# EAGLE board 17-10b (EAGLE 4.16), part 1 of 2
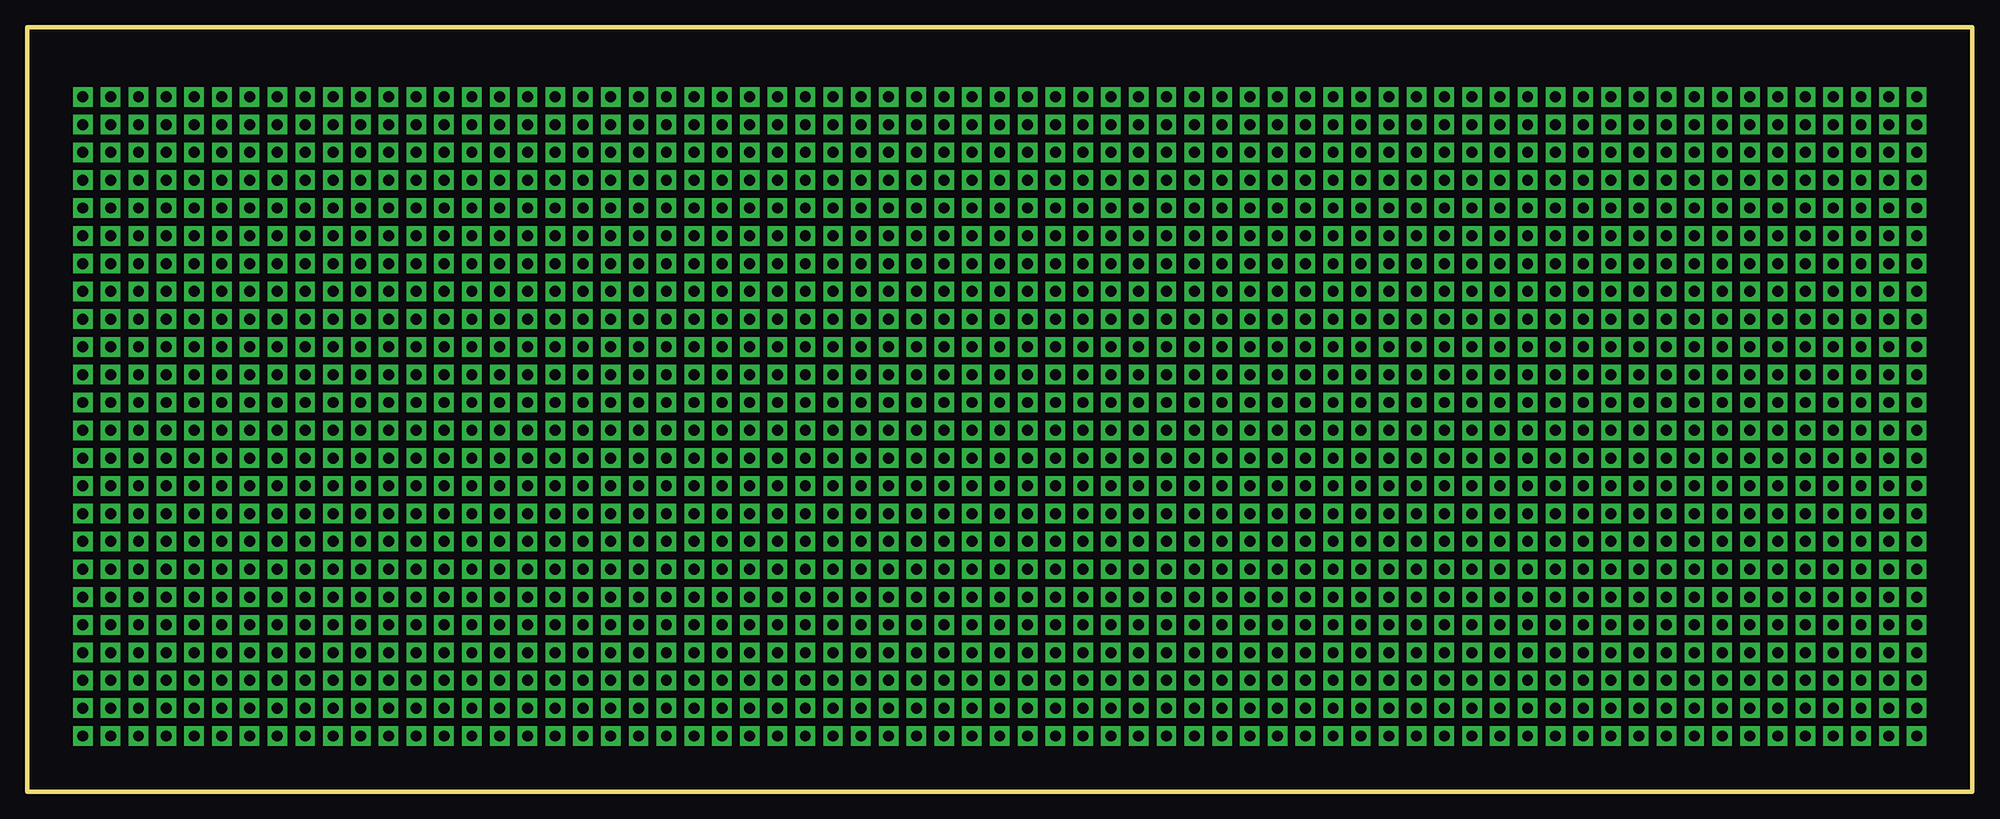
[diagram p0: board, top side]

Size 177.8 x 69.85 mm. Coordinates in mm from the lower left corner, seen from the top.
Outline: 0,0 0,69.85 177.8,69.85 177.8,0 0,0
Copper layers (1*16): Top 0.035mm / dielectric 1.5mm / Bottom 0.035mm
Design rules "default": minimum track width 10mil, minimum drill 24mil, track to track 8mil, track to pad 8mil, pad to pad 8mil, via to via 8mil, smd to smd 8mil, copper to edge 40mil, drill to drill 8mil, minimum pad ring 10mil, minimum via ring 8mil, stop-mask expansion 4mil, vias tented up to drill 0mil, thermal gap 10mil

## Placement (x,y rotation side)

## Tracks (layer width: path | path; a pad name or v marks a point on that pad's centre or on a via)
S$1  (via drill 1 pad 1.78)
  other vias: 5.08,5.08
S$2  (via drill 1 pad 1.78)
  other vias: 5.08,7.62
S$3  (via drill 1 pad 1.78)
  other vias: 5.08,10.16
S$4  (via drill 1 pad 1.78)
  other vias: 5.08,12.7
S$5  (via drill 1 pad 1.78)
  other vias: 5.08,15.24
S$6  (via drill 1 pad 1.78)
  other vias: 5.08,17.78
S$7  (via drill 1 pad 1.78)
  other vias: 5.08,20.32
S$8  (via drill 1 pad 1.78)
  other vias: 5.08,22.86
S$9  (via drill 1 pad 1.78)
  other vias: 5.08,25.4
S$10  (via drill 1 pad 1.78)
  other vias: 5.08,27.94
S$11  (via drill 1 pad 1.78)
  other vias: 5.08,30.48
S$12  (via drill 1 pad 1.78)
  other vias: 5.08,33.02
S$13  (via drill 1 pad 1.78)
  other vias: 5.08,35.56
S$14  (via drill 1 pad 1.78)
  other vias: 5.08,38.1
S$15  (via drill 1 pad 1.78)
  other vias: 5.08,40.64
S$16  (via drill 1 pad 1.78)
  other vias: 5.08,43.18
S$17  (via drill 1 pad 1.78)
  other vias: 5.08,45.72
S$18  (via drill 1 pad 1.78)
  other vias: 5.08,48.26
S$19  (via drill 1 pad 1.78)
  other vias: 5.08,50.8
S$20  (via drill 1 pad 1.78)
  other vias: 5.08,53.34
S$21  (via drill 1 pad 1.78)
  other vias: 5.08,55.88
S$22  (via drill 1 pad 1.78)
  other vias: 5.08,58.42
S$23  (via drill 1 pad 1.78)
  other vias: 5.08,60.96
S$24  (via drill 1 pad 1.78)
  other vias: 5.08,63.5
S$25  (via drill 1 pad 1.78)
  other vias: 7.62,63.5
S$26  (via drill 1 pad 1.78)
  other vias: 7.62,60.96
S$27  (via drill 1 pad 1.78)
  other vias: 7.62,58.42
S$28  (via drill 1 pad 1.78)
  other vias: 7.62,55.88
S$29  (via drill 1 pad 1.78)
  other vias: 7.62,53.34
S$30  (via drill 1 pad 1.78)
  other vias: 7.62,50.8
S$31  (via drill 1 pad 1.78)
  other vias: 7.62,48.26
S$32  (via drill 1 pad 1.78)
  other vias: 7.62,45.72
S$33  (via drill 1 pad 1.78)
  other vias: 7.62,43.18
S$34  (via drill 1 pad 1.78)
  other vias: 7.62,40.64
S$35  (via drill 1 pad 1.78)
  other vias: 7.62,38.1
S$36  (via drill 1 pad 1.78)
  other vias: 7.62,35.56
S$37  (via drill 1 pad 1.78)
  other vias: 7.62,33.02
S$38  (via drill 1 pad 1.78)
  other vias: 7.62,30.48
S$39  (via drill 1 pad 1.78)
  other vias: 7.62,27.94
S$40  (via drill 1 pad 1.78)
  other vias: 7.62,25.4
S$41  (via drill 1 pad 1.78)
  other vias: 7.62,22.86
S$42  (via drill 1 pad 1.78)
  other vias: 7.62,20.32
S$43  (via drill 1 pad 1.78)
  other vias: 7.62,17.78
S$44  (via drill 1 pad 1.78)
  other vias: 7.62,15.24
S$45  (via drill 1 pad 1.78)
  other vias: 7.62,12.7
S$46  (via drill 1 pad 1.78)
  other vias: 7.62,10.16
S$47  (via drill 1 pad 1.78)
  other vias: 7.62,7.62
S$48  (via drill 1 pad 1.78)
  other vias: 7.62,5.08
S$49  (via drill 1 pad 1.78)
  other vias: 10.16,5.08
S$50  (via drill 1 pad 1.78)
  other vias: 12.7,5.08
S$51  (via drill 1 pad 1.78)
  other vias: 15.24,5.08
S$52  (via drill 1 pad 1.78)
  other vias: 17.78,5.08
S$53  (via drill 1 pad 1.78)
  other vias: 20.32,5.08
S$54  (via drill 1 pad 1.78)
  other vias: 22.86,5.08
S$55  (via drill 1 pad 1.78)
  other vias: 25.4,5.08
S$56  (via drill 1 pad 1.78)
  other vias: 30.48,5.08
S$57  (via drill 1 pad 1.78)
  other vias: 27.94,5.08
S$58  (via drill 1 pad 1.78)
  other vias: 33.02,5.08
S$59  (via drill 1 pad 1.78)
  other vias: 38.1,5.08
S$60  (via drill 1 pad 1.78)
  other vias: 35.56,5.08
S$61  (via drill 1 pad 1.78)
  other vias: 40.64,5.08
S$62  (via drill 1 pad 1.78)
  other vias: 43.18,5.08
S$63  (via drill 1 pad 1.78)
  other vias: 45.72,5.08
S$64  (via drill 1 pad 1.78)
  other vias: 48.26,5.08
S$65  (via drill 1 pad 1.78)
  other vias: 50.8,5.08
S$66  (via drill 1 pad 1.78)
  other vias: 55.88,5.08
S$67  (via drill 1 pad 1.78)
  other vias: 53.34,5.08
S$68  (via drill 1 pad 1.78)
  other vias: 58.42,5.08
S$69  (via drill 1 pad 1.78)
  other vias: 60.96,5.08
S$70  (via drill 1 pad 1.78)
  other vias: 63.5,5.08
S$71  (via drill 1 pad 1.78)
  other vias: 66.04,5.08
S$72  (via drill 1 pad 1.78)
  other vias: 71.12,5.08
S$73  (via drill 1 pad 1.78)
  other vias: 68.58,5.08
S$74  (via drill 1 pad 1.78)
  other vias: 172.72,5.08
S$75  (via drill 1 pad 1.78)
  other vias: 172.72,7.62
S$76  (via drill 1 pad 1.78)
  other vias: 172.72,10.16
S$77  (via drill 1 pad 1.78)
  other vias: 172.72,12.7
S$78  (via drill 1 pad 1.78)
  other vias: 172.72,15.24
S$79  (via drill 1 pad 1.78)
  other vias: 172.72,17.78
S$80  (via drill 1 pad 1.78)
  other vias: 172.72,20.32
S$81  (via drill 1 pad 1.78)
  other vias: 172.72,22.86
S$82  (via drill 1 pad 1.78)
  other vias: 172.72,27.94
S$83  (via drill 1 pad 1.78)
  other vias: 172.72,25.4
S$84  (via drill 1 pad 1.78)
  other vias: 172.72,30.48
S$85  (via drill 1 pad 1.78)
  other vias: 172.72,33.02
S$86  (via drill 1 pad 1.78)
  other vias: 172.72,35.56
S$87  (via drill 1 pad 1.78)
  other vias: 172.72,38.1
S$88  (via drill 1 pad 1.78)
  other vias: 172.72,40.64
S$89  (via drill 1 pad 1.78)
  other vias: 172.72,43.18
S$90  (via drill 1 pad 1.78)
  other vias: 172.72,45.72
S$91  (via drill 1 pad 1.78)
  other vias: 172.72,48.26
S$92  (via drill 1 pad 1.78)
  other vias: 172.72,50.8
S$93  (via drill 1 pad 1.78)
  other vias: 172.72,53.34
S$94  (via drill 1 pad 1.78)
  other vias: 172.72,55.88
S$95  (via drill 1 pad 1.78)
  other vias: 172.72,58.42
S$96  (via drill 1 pad 1.78)
  other vias: 172.72,60.96
S$97  (via drill 1 pad 1.78)
  other vias: 172.72,63.5
S$98  (via drill 1 pad 1.78)
  other vias: 170.18,63.5
S$99  (via drill 1 pad 1.78)
  other vias: 167.64,63.5
S$100  (via drill 1 pad 1.78)
  other vias: 165.1,63.5
S$101  (via drill 1 pad 1.78)
  other vias: 162.56,63.5
S$102  (via drill 1 pad 1.78)
  other vias: 160.02,63.5
S$103  (via drill 1 pad 1.78)
  other vias: 157.48,63.5
S$104  (via drill 1 pad 1.78)
  other vias: 152.4,63.5
S$105  (via drill 1 pad 1.78)
  other vias: 154.94,63.5
S$106  (via drill 1 pad 1.78)
  other vias: 149.86,60.96
S$107  (via drill 1 pad 1.78)
  other vias: 149.86,63.5
S$108  (via drill 1 pad 1.78)
  other vias: 147.32,63.5
S$109  (via drill 1 pad 1.78)
  other vias: 142.24,63.5
S$110  (via drill 1 pad 1.78)
  other vias: 137.16,63.5
S$111  (via drill 1 pad 1.78)
  other vias: 132.08,63.5
S$112  (via drill 1 pad 1.78)
  other vias: 10.16,63.5
S$113  (via drill 1 pad 1.78)
  other vias: 12.7,63.5
S$114  (via drill 1 pad 1.78)
  other vias: 15.24,63.5
S$115  (via drill 1 pad 1.78)
  other vias: 17.78,60.96
S$116  (via drill 1 pad 1.78)
  other vias: 17.78,63.5
S$117  (via drill 1 pad 1.78)
  other vias: 20.32,63.5
S$118  (via drill 1 pad 1.78)
  other vias: 22.86,63.5
S$119  (via drill 1 pad 1.78)
  other vias: 25.4,63.5
S$120  (via drill 1 pad 1.78)
  other vias: 27.94,60.96
S$121  (via drill 1 pad 1.78)
  other vias: 27.94,63.5
S$122  (via drill 1 pad 1.78)
  other vias: 30.48,63.5
S$123  (via drill 1 pad 1.78)
  other vias: 33.02,63.5
S$124  (via drill 1 pad 1.78)
  other vias: 35.56,63.5
S$125  (via drill 1 pad 1.78)
  other vias: 38.1,63.5
S$126  (via drill 1 pad 1.78)
  other vias: 40.64,63.5
S$127  (via drill 1 pad 1.78)
  other vias: 43.18,63.5
S$128  (via drill 1 pad 1.78)
  other vias: 45.72,63.5
S$129  (via drill 1 pad 1.78)
  other vias: 48.26,63.5
S$130  (via drill 1 pad 1.78)
  other vias: 50.8,63.5
S$131  (via drill 1 pad 1.78)
  other vias: 53.34,63.5
S$132  (via drill 1 pad 1.78)
  other vias: 55.88,63.5
S$133  (via drill 1 pad 1.78)
  other vias: 58.42,63.5
S$134  (via drill 1 pad 1.78)
  other vias: 63.5,63.5
S$135  (via drill 1 pad 1.78)
  other vias: 66.04,63.5
S$136  (via drill 1 pad 1.78)
  other vias: 68.58,60.96
S$137  (via drill 1 pad 1.78)
  other vias: 73.66,63.5
S$138  (via drill 1 pad 1.78)
  other vias: 81.28,63.5
S$139  (via drill 1 pad 1.78)
  other vias: 81.28,60.96
S$140  (via drill 1 pad 1.78)
  other vias: 96.52,63.5
S$141  (via drill 1 pad 1.78)
  other vias: 101.6,60.96
S$142  (via drill 1 pad 1.78)
  other vias: 111.76,60.96
S$143  (via drill 1 pad 1.78)
  other vias: 114.3,60.96
S$144  (via drill 1 pad 1.78)
  other vias: 129.54,63.5
S$145  (via drill 1 pad 1.78)
  other vias: 127,63.5
S$146  (via drill 1 pad 1.78)
  other vias: 124.46,63.5
S$147  (via drill 1 pad 1.78)
  other vias: 121.92,63.5
S$148  (via drill 1 pad 1.78)
  other vias: 116.84,63.5
S$149  (via drill 1 pad 1.78)
  other vias: 119.38,63.5
S$150  (via drill 1 pad 1.78)
  other vias: 114.3,63.5
S$151  (via drill 1 pad 1.78)
  other vias: 111.76,63.5
S$152  (via drill 1 pad 1.78)
  other vias: 109.22,63.5
S$153  (via drill 1 pad 1.78)
  other vias: 106.68,63.5
S$154  (via drill 1 pad 1.78)
  other vias: 104.14,63.5
S$155  (via drill 1 pad 1.78)
  other vias: 101.6,63.5
S$156  (via drill 1 pad 1.78)
  other vias: 99.06,63.5
S$157  (via drill 1 pad 1.78)
  other vias: 93.98,63.5
S$158  (via drill 1 pad 1.78)
  other vias: 91.44,63.5
S$159  (via drill 1 pad 1.78)
  other vias: 88.9,63.5
S$160  (via drill 1 pad 1.78)
  other vias: 86.36,63.5
S$161  (via drill 1 pad 1.78)
  other vias: 83.82,63.5
S$162  (via drill 1 pad 1.78)
  other vias: 78.74,63.5
S$163  (via drill 1 pad 1.78)
  other vias: 76.2,63.5
S$164  (via drill 1 pad 1.78)
  other vias: 71.12,63.5
S$165  (via drill 1 pad 1.78)
  other vias: 68.58,63.5
S$166  (via drill 1 pad 1.78)
  other vias: 60.96,63.5
S$167  (via drill 1 pad 1.78)
  other vias: 134.62,63.5
S$168  (via drill 1 pad 1.78)
  other vias: 139.7,63.5
S$169  (via drill 1 pad 1.78)
  other vias: 144.78,63.5
S$170  (via drill 1 pad 1.78)
  other vias: 73.66,5.08
S$171  (via drill 1 pad 1.78)
  other vias: 76.2,5.08
S$172  (via drill 1 pad 1.78)
  other vias: 78.74,5.08
S$173  (via drill 1 pad 1.78)
  other vias: 81.28,5.08
S$174  (via drill 1 pad 1.78)
  other vias: 83.82,5.08
S$175  (via drill 1 pad 1.78)
  other vias: 86.36,5.08
S$176  (via drill 1 pad 1.78)
  other vias: 88.9,5.08
S$177  (via drill 1 pad 1.78)
  other vias: 91.44,5.08
S$178  (via drill 1 pad 1.78)
  other vias: 93.98,5.08
S$179  (via drill 1 pad 1.78)
  other vias: 96.52,5.08
S$180  (via drill 1 pad 1.78)
  other vias: 99.06,5.08
S$181  (via drill 1 pad 1.78)
  other vias: 101.6,5.08
S$182  (via drill 1 pad 1.78)
  other vias: 170.18,5.08
S$183  (via drill 1 pad 1.78)
  other vias: 167.64,5.08
S$184  (via drill 1 pad 1.78)
  other vias: 165.1,5.08
S$185  (via drill 1 pad 1.78)
  other vias: 162.56,5.08
S$186  (via drill 1 pad 1.78)
  other vias: 160.02,5.08
S$187  (via drill 1 pad 1.78)
  other vias: 157.48,5.08
S$188  (via drill 1 pad 1.78)
  other vias: 154.94,5.08
S$189  (via drill 1 pad 1.78)
  other vias: 152.4,5.08
S$190  (via drill 1 pad 1.78)
  other vias: 149.86,5.08
S$191  (via drill 1 pad 1.78)
  other vias: 147.32,5.08
S$192  (via drill 1 pad 1.78)
  other vias: 144.78,5.08
S$193  (via drill 1 pad 1.78)
  other vias: 142.24,5.08
S$194  (via drill 1 pad 1.78)
  other vias: 139.7,5.08
S$195  (via drill 1 pad 1.78)
  other vias: 137.16,5.08
S$196  (via drill 1 pad 1.78)
  other vias: 134.62,5.08
S$197  (via drill 1 pad 1.78)
  other vias: 132.08,5.08
S$198  (via drill 1 pad 1.78)
  other vias: 129.54,5.08
S$199  (via drill 1 pad 1.78)
  other vias: 127,5.08
S$200  (via drill 1 pad 1.78)
  other vias: 124.46,5.08
S$201  (via drill 1 pad 1.78)
  other vias: 121.92,5.08
S$202  (via drill 1 pad 1.78)
  other vias: 119.38,5.08
S$203  (via drill 1 pad 1.78)
  other vias: 116.84,5.08
S$204  (via drill 1 pad 1.78)
  other vias: 114.3,5.08
S$205  (via drill 1 pad 1.78)
  other vias: 111.76,5.08
S$206  (via drill 1 pad 1.78)
  other vias: 109.22,5.08
S$207  (via drill 1 pad 1.78)
  other vias: 106.68,5.08
S$208  (via drill 1 pad 1.78)
  other vias: 104.14,5.08
S$209  (via drill 1 pad 1.78)
  other vias: 170.18,60.96
S$210  (via drill 1 pad 1.78)
  other vias: 170.18,58.42
S$211  (via drill 1 pad 1.78)
  other vias: 170.18,55.88
S$212  (via drill 1 pad 1.78)
  other vias: 170.18,53.34
S$213  (via drill 1 pad 1.78)
  other vias: 170.18,50.8
S$214  (via drill 1 pad 1.78)
  other vias: 170.18,48.26
S$215  (via drill 1 pad 1.78)
  other vias: 170.18,45.72
S$216  (via drill 1 pad 1.78)
  other vias: 170.18,43.18
S$217  (via drill 1 pad 1.78)
  other vias: 170.18,40.64
S$218  (via drill 1 pad 1.78)
  other vias: 170.18,38.1
S$219  (via drill 1 pad 1.78)
  other vias: 170.18,35.56
S$220  (via drill 1 pad 1.78)
  other vias: 170.18,33.02
S$221  (via drill 1 pad 1.78)
  other vias: 170.18,30.48
S$222  (via drill 1 pad 1.78)
  other vias: 170.18,27.94
S$223  (via drill 1 pad 1.78)
  other vias: 170.18,25.4
S$224  (via drill 1 pad 1.78)
  other vias: 170.18,22.86
S$225  (via drill 1 pad 1.78)
  other vias: 170.18,20.32
S$226  (via drill 1 pad 1.78)
  other vias: 170.18,17.78
S$227  (via drill 1 pad 1.78)
  other vias: 170.18,15.24
S$228  (via drill 1 pad 1.78)
  other vias: 170.18,12.7
S$229  (via drill 1 pad 1.78)
  other vias: 170.18,10.16
S$230  (via drill 1 pad 1.78)
  other vias: 170.18,7.62
S$231  (via drill 1 pad 1.78)
  other vias: 167.64,7.62
S$232  (via drill 1 pad 1.78)
  other vias: 165.1,7.62
S$233  (via drill 1 pad 1.78)
  other vias: 162.56,7.62
S$234  (via drill 1 pad 1.78)
  other vias: 157.48,7.62
S$235  (via drill 1 pad 1.78)
  other vias: 160.02,7.62
S$236  (via drill 1 pad 1.78)
  other vias: 154.94,7.62
S$237  (via drill 1 pad 1.78)
  other vias: 152.4,7.62
S$238  (via drill 1 pad 1.78)
  other vias: 149.86,7.62
S$239  (via drill 1 pad 1.78)
  other vias: 147.32,7.62
S$240  (via drill 1 pad 1.78)
  other vias: 144.78,7.62
S$241  (via drill 1 pad 1.78)
  other vias: 12.7,7.62
S$242  (via drill 1 pad 1.78)
  other vias: 10.16,7.62
S$243  (via drill 1 pad 1.78)
  other vias: 15.24,7.62
S$244  (via drill 1 pad 1.78)
  other vias: 17.78,7.62
S$245  (via drill 1 pad 1.78)
  other vias: 20.32,7.62
S$246  (via drill 1 pad 1.78)
  other vias: 22.86,7.62
S$247  (via drill 1 pad 1.78)
  other vias: 25.4,7.62
S$248  (via drill 1 pad 1.78)
  other vias: 27.94,7.62
S$249  (via drill 1 pad 1.78)
  other vias: 30.48,7.62
S$250  (via drill 1 pad 1.78)
  other vias: 33.02,7.62
S$251  (via drill 1 pad 1.78)
  other vias: 35.56,7.62
S$252  (via drill 1 pad 1.78)
  other vias: 38.1,7.62
S$253  (via drill 1 pad 1.78)
  other vias: 40.64,7.62
S$254  (via drill 1 pad 1.78)
  other vias: 43.18,7.62
S$255  (via drill 1 pad 1.78)
  other vias: 45.72,7.62
S$256  (via drill 1 pad 1.78)
  other vias: 48.26,7.62
S$257  (via drill 1 pad 1.78)
  other vias: 50.8,7.62
S$258  (via drill 1 pad 1.78)
  other vias: 53.34,7.62
S$259  (via drill 1 pad 1.78)
  other vias: 55.88,7.62
S$260  (via drill 1 pad 1.78)
  other vias: 58.42,7.62
S$261  (via drill 1 pad 1.78)
  other vias: 60.96,7.62
S$262  (via drill 1 pad 1.78)
  other vias: 63.5,7.62
S$263  (via drill 1 pad 1.78)
  other vias: 66.04,7.62
S$264  (via drill 1 pad 1.78)
  other vias: 68.58,7.62
S$265  (via drill 1 pad 1.78)
  other vias: 71.12,7.62
S$266  (via drill 1 pad 1.78)
  other vias: 73.66,7.62
S$267  (via drill 1 pad 1.78)
  other vias: 76.2,7.62
S$268  (via drill 1 pad 1.78)
  other vias: 78.74,7.62
S$269  (via drill 1 pad 1.78)
  other vias: 81.28,7.62
S$270  (via drill 1 pad 1.78)
  other vias: 86.36,7.62
S$271  (via drill 1 pad 1.78)
  other vias: 83.82,7.62
S$272  (via drill 1 pad 1.78)
  other vias: 88.9,7.62
S$273  (via drill 1 pad 1.78)
  other vias: 91.44,7.62
S$274  (via drill 1 pad 1.78)
  other vias: 93.98,7.62
S$275  (via drill 1 pad 1.78)
  other vias: 96.52,7.62
S$276  (via drill 1 pad 1.78)
  other vias: 99.06,7.62
S$277  (via drill 1 pad 1.78)
  other vias: 101.6,7.62
S$278  (via drill 1 pad 1.78)
  other vias: 104.14,7.62
S$279  (via drill 1 pad 1.78)
  other vias: 109.22,7.62
S$280  (via drill 1 pad 1.78)
  other vias: 106.68,7.62
S$281  (via drill 1 pad 1.78)
  other vias: 111.76,7.62
S$282  (via drill 1 pad 1.78)
  other vias: 114.3,7.62
S$283  (via drill 1 pad 1.78)
  other vias: 142.24,7.62
S$284  (via drill 1 pad 1.78)
  other vias: 139.7,7.62
S$285  (via drill 1 pad 1.78)
  other vias: 137.16,7.62
S$286  (via drill 1 pad 1.78)
  other vias: 134.62,7.62
S$287  (via drill 1 pad 1.78)
  other vias: 132.08,7.62
S$288  (via drill 1 pad 1.78)
  other vias: 129.54,7.62
S$289  (via drill 1 pad 1.78)
  other vias: 127,7.62
S$290  (via drill 1 pad 1.78)
  other vias: 124.46,7.62
S$291  (via drill 1 pad 1.78)
  other vias: 121.92,7.62
S$292  (via drill 1 pad 1.78)
  other vias: 119.38,7.62
S$293  (via drill 1 pad 1.78)
  other vias: 116.84,7.62
S$294  (via drill 1 pad 1.78)
  other vias: 10.16,60.96
S$295  (via drill 1 pad 1.78)
  other vias: 12.7,60.96
S$296  (via drill 1 pad 1.78)
  other vias: 15.24,60.96
S$297  (via drill 1 pad 1.78)
  other vias: 20.32,60.96
S$298  (via drill 1 pad 1.78)
  other vias: 22.86,60.96
S$299  (via drill 1 pad 1.78)
  other vias: 25.4,60.96
S$300  (via drill 1 pad 1.78)
  other vias: 30.48,60.96
S$301  (via drill 1 pad 1.78)
  other vias: 33.02,60.96
S$302  (via drill 1 pad 1.78)
  other vias: 35.56,60.96
S$303  (via drill 1 pad 1.78)
  other vias: 38.1,60.96
S$304  (via drill 1 pad 1.78)
  other vias: 40.64,60.96
S$305  (via drill 1 pad 1.78)
  other vias: 43.18,60.96
S$306  (via drill 1 pad 1.78)
  other vias: 45.72,60.96
S$307  (via drill 1 pad 1.78)
  other vias: 48.26,60.96
S$308  (via drill 1 pad 1.78)
  other vias: 50.8,60.96
S$309  (via drill 1 pad 1.78)
  other vias: 53.34,60.96
S$310  (via drill 1 pad 1.78)
  other vias: 55.88,60.96
S$311  (via drill 1 pad 1.78)
  other vias: 58.42,60.96
S$312  (via drill 1 pad 1.78)
  other vias: 60.96,60.96
S$313  (via drill 1 pad 1.78)
  other vias: 63.5,60.96
S$314  (via drill 1 pad 1.78)
  other vias: 66.04,60.96
S$315  (via drill 1 pad 1.78)
  other vias: 71.12,60.96
S$316  (via drill 1 pad 1.78)
  other vias: 73.66,60.96
S$317  (via drill 1 pad 1.78)
  other vias: 76.2,60.96
S$318  (via drill 1 pad 1.78)
  other vias: 78.74,60.96
S$319  (via drill 1 pad 1.78)
  other vias: 83.82,60.96
S$320  (via drill 1 pad 1.78)
  other vias: 86.36,60.96
S$321  (via drill 1 pad 1.78)
  other vias: 88.9,60.96
S$322  (via drill 1 pad 1.78)
  other vias: 91.44,60.96
S$323  (via drill 1 pad 1.78)
  other vias: 93.98,60.96
S$324  (via drill 1 pad 1.78)
  other vias: 96.52,60.96
S$325  (via drill 1 pad 1.78)
  other vias: 99.06,60.96
S$326  (via drill 1 pad 1.78)
  other vias: 104.14,60.96
S$327  (via drill 1 pad 1.78)
  other vias: 106.68,60.96
S$328  (via drill 1 pad 1.78)
  other vias: 109.22,60.96
S$329  (via drill 1 pad 1.78)
  other vias: 116.84,60.96
S$330  (via drill 1 pad 1.78)
  other vias: 167.64,60.96
S$331  (via drill 1 pad 1.78)
  other vias: 165.1,60.96
S$332  (via drill 1 pad 1.78)
  other vias: 162.56,60.96
S$333  (via drill 1 pad 1.78)
  other vias: 160.02,60.96
S$334  (via drill 1 pad 1.78)
  other vias: 157.48,60.96
S$335  (via drill 1 pad 1.78)
  other vias: 154.94,60.96
S$336  (via drill 1 pad 1.78)
  other vias: 152.4,60.96
S$337  (via drill 1 pad 1.78)
  other vias: 147.32,60.96
S$338  (via drill 1 pad 1.78)
  other vias: 144.78,60.96
S$339  (via drill 1 pad 1.78)
  other vias: 142.24,60.96
S$340  (via drill 1 pad 1.78)
  other vias: 139.7,60.96
S$341  (via drill 1 pad 1.78)
  other vias: 137.16,60.96
S$342  (via drill 1 pad 1.78)
  other vias: 134.62,60.96
S$343  (via drill 1 pad 1.78)
  other vias: 132.08,60.96
S$344  (via drill 1 pad 1.78)
  other vias: 129.54,60.96
S$345  (via drill 1 pad 1.78)
  other vias: 127,60.96
S$346  (via drill 1 pad 1.78)
  other vias: 124.46,60.96
S$347  (via drill 1 pad 1.78)
  other vias: 121.92,60.96
S$348  (via drill 1 pad 1.78)
  other vias: 119.38,60.96
S$349  (via drill 1 pad 1.78)
  other vias: 167.64,58.42
S$350  (via drill 1 pad 1.78)
  other vias: 167.64,55.88
S$351  (via drill 1 pad 1.78)
  other vias: 167.64,53.34
S$352  (via drill 1 pad 1.78)
  other vias: 167.64,50.8
S$353  (via drill 1 pad 1.78)
  other vias: 167.64,48.26
S$354  (via drill 1 pad 1.78)
  other vias: 167.64,45.72
S$355  (via drill 1 pad 1.78)
  other vias: 167.64,43.18
S$356  (via drill 1 pad 1.78)
  other vias: 167.64,40.64
S$357  (via drill 1 pad 1.78)
  other vias: 167.64,38.1
S$358  (via drill 1 pad 1.78)
  other vias: 167.64,33.02
S$359  (via drill 1 pad 1.78)
  other vias: 167.64,35.56
S$360  (via drill 1 pad 1.78)
  other vias: 167.64,30.48
S$361  (via drill 1 pad 1.78)
  other vias: 167.64,27.94
S$362  (via drill 1 pad 1.78)
  other vias: 167.64,25.4
S$363  (via drill 1 pad 1.78)
  other vias: 167.64,22.86
S$364  (via drill 1 pad 1.78)
  other vias: 167.64,20.32
S$365  (via drill 1 pad 1.78)
  other vias: 167.64,17.78
S$366  (via drill 1 pad 1.78)
  other vias: 167.64,15.24
S$367  (via drill 1 pad 1.78)
  other vias: 167.64,12.7
S$368  (via drill 1 pad 1.78)
  other vias: 167.64,10.16
S$369  (via drill 1 pad 1.78)
  other vias: 10.16,58.42
S$370  (via drill 1 pad 1.78)
  other vias: 10.16,53.34
S$371  (via drill 1 pad 1.78)
  other vias: 10.16,55.88
S$372  (via drill 1 pad 1.78)
  other vias: 10.16,50.8
S$373  (via drill 1 pad 1.78)
  other vias: 10.16,48.26
S$374  (via drill 1 pad 1.78)
  other vias: 10.16,45.72
S$375  (via drill 1 pad 1.78)
  other vias: 10.16,43.18
S$376  (via drill 1 pad 1.78)
  other vias: 10.16,40.64
S$377  (via drill 1 pad 1.78)
  other vias: 10.16,38.1
S$378  (via drill 1 pad 1.78)
  other vias: 10.16,35.56
S$379  (via drill 1 pad 1.78)
  other vias: 10.16,33.02
S$380  (via drill 1 pad 1.78)
  other vias: 10.16,30.48
S$381  (via drill 1 pad 1.78)
  other vias: 10.16,27.94
S$382  (via drill 1 pad 1.78)
  other vias: 10.16,25.4
S$383  (via drill 1 pad 1.78)
  other vias: 10.16,22.86
S$384  (via drill 1 pad 1.78)
  other vias: 10.16,20.32
S$385  (via drill 1 pad 1.78)
  other vias: 10.16,17.78
S$386  (via drill 1 pad 1.78)
  other vias: 10.16,15.24
S$387  (via drill 1 pad 1.78)
  other vias: 10.16,12.7
S$388  (via drill 1 pad 1.78)
  other vias: 12.7,10.16
S$389  (via drill 1 pad 1.78)
  other vias: 10.16,10.16
S$390  (via drill 1 pad 1.78)
  other vias: 15.24,10.16
S$391  (via drill 1 pad 1.78)
  other vias: 17.78,10.16
S$392  (via drill 1 pad 1.78)
  other vias: 20.32,10.16
S$393  (via drill 1 pad 1.78)
  other vias: 22.86,10.16
S$394  (via drill 1 pad 1.78)
  other vias: 25.4,10.16
S$395  (via drill 1 pad 1.78)
  other vias: 27.94,10.16
S$396  (via drill 1 pad 1.78)
  other vias: 30.48,10.16
S$397  (via drill 1 pad 1.78)
  other vias: 33.02,10.16
S$398  (via drill 1 pad 1.78)
  other vias: 35.56,10.16
S$399  (via drill 1 pad 1.78)
  other vias: 38.1,10.16
S$400  (via drill 1 pad 1.78)
  other vias: 40.64,10.16
S$401  (via drill 1 pad 1.78)
  other vias: 43.18,10.16
S$402  (via drill 1 pad 1.78)
  other vias: 45.72,10.16
S$403  (via drill 1 pad 1.78)
  other vias: 50.8,10.16
S$404  (via drill 1 pad 1.78)
  other vias: 48.26,10.16
S$405  (via drill 1 pad 1.78)
  other vias: 53.34,10.16
S$406  (via drill 1 pad 1.78)
  other vias: 55.88,10.16
S$407  (via drill 1 pad 1.78)
  other vias: 58.42,10.16
S$408  (via drill 1 pad 1.78)
  other vias: 60.96,10.16
S$409  (via drill 1 pad 1.78)
  other vias: 63.5,10.16
S$410  (via drill 1 pad 1.78)
  other vias: 68.58,10.16
S$411  (via drill 1 pad 1.78)
  other vias: 66.04,10.16
S$412  (via drill 1 pad 1.78)
  other vias: 73.66,10.16
S$413  (via drill 1 pad 1.78)
  other vias: 71.12,10.16
S$414  (via drill 1 pad 1.78)
  other vias: 76.2,10.16
S$415  (via drill 1 pad 1.78)
  other vias: 78.74,10.16
S$416  (via drill 1 pad 1.78)
  other vias: 81.28,10.16
S$417  (via drill 1 pad 1.78)
  other vias: 83.82,10.16
S$418  (via drill 1 pad 1.78)
  other vias: 86.36,10.16
S$419  (via drill 1 pad 1.78)
  other vias: 88.9,10.16
S$420  (via drill 1 pad 1.78)
  other vias: 91.44,10.16
S$421  (via drill 1 pad 1.78)
  other vias: 93.98,10.16
S$422  (via drill 1 pad 1.78)
  other vias: 96.52,10.16
S$423  (via drill 1 pad 1.78)
  other vias: 99.06,10.16
S$424  (via drill 1 pad 1.78)
  other vias: 101.6,10.16
S$425  (via drill 1 pad 1.78)
  other vias: 104.14,10.16
S$426  (via drill 1 pad 1.78)
  other vias: 106.68,10.16
S$427  (via drill 1 pad 1.78)
  other vias: 109.22,10.16
S$428  (via drill 1 pad 1.78)
  other vias: 111.76,10.16
S$429  (via drill 1 pad 1.78)
  other vias: 114.3,10.16
S$430  (via drill 1 pad 1.78)
  other vias: 116.84,10.16
S$431  (via drill 1 pad 1.78)
  other vias: 119.38,10.16
S$432  (via drill 1 pad 1.78)
  other vias: 121.92,10.16
S$433  (via drill 1 pad 1.78)
  other vias: 127,10.16
S$434  (via drill 1 pad 1.78)
  other vias: 124.46,10.16
S$435  (via drill 1 pad 1.78)
  other vias: 129.54,10.16
S$436  (via drill 1 pad 1.78)
  other vias: 132.08,10.16
S$437  (via drill 1 pad 1.78)
  other vias: 134.62,10.16
S$438  (via drill 1 pad 1.78)
  other vias: 137.16,10.16
S$439  (via drill 1 pad 1.78)
  other vias: 139.7,10.16
S$440  (via drill 1 pad 1.78)
  other vias: 142.24,10.16
S$441  (via drill 1 pad 1.78)
  other vias: 144.78,10.16
S$442  (via drill 1 pad 1.78)
  other vias: 147.32,10.16
S$443  (via drill 1 pad 1.78)
  other vias: 149.86,10.16
S$444  (via drill 1 pad 1.78)
  other vias: 152.4,10.16
S$445  (via drill 1 pad 1.78)
  other vias: 157.48,10.16
S$446  (via drill 1 pad 1.78)
  other vias: 154.94,10.16
S$447  (via drill 1 pad 1.78)
  other vias: 160.02,10.16
S$448  (via drill 1 pad 1.78)
  other vias: 162.56,10.16
S$449  (via drill 1 pad 1.78)
  other vias: 165.1,10.16
S$450  (via drill 1 pad 1.78)
  other vias: 165.1,58.42
S$451  (via drill 1 pad 1.78)
  other vias: 162.56,58.42
S$452  (via drill 1 pad 1.78)
  other vias: 160.02,58.42
S$453  (via drill 1 pad 1.78)
  other vias: 157.48,58.42
S$454  (via drill 1 pad 1.78)
  other vias: 154.94,58.42
S$455  (via drill 1 pad 1.78)
  other vias: 152.4,58.42
S$456  (via drill 1 pad 1.78)
  other vias: 149.86,58.42
S$457  (via drill 1 pad 1.78)
  other vias: 144.78,58.42
S$458  (via drill 1 pad 1.78)
  other vias: 147.32,58.42
S$459  (via drill 1 pad 1.78)
  other vias: 144.78,55.88
S$460  (via drill 1 pad 1.78)
  other vias: 142.24,58.42
S$461  (via drill 1 pad 1.78)
  other vias: 139.7,58.42
S$462  (via drill 1 pad 1.78)
  other vias: 12.7,58.42
S$463  (via drill 1 pad 1.78)
  other vias: 15.24,58.42
S$464  (via drill 1 pad 1.78)
  other vias: 17.78,58.42
S$465  (via drill 1 pad 1.78)
  other vias: 20.32,58.42
S$466  (via drill 1 pad 1.78)
  other vias: 22.86,58.42
S$467  (via drill 1 pad 1.78)
  other vias: 25.4,58.42
S$468  (via drill 1 pad 1.78)
  other vias: 30.48,58.42
S$469  (via drill 1 pad 1.78)
  other vias: 27.94,58.42
S$470  (via drill 1 pad 1.78)
  other vias: 33.02,58.42
S$471  (via drill 1 pad 1.78)
  other vias: 35.56,55.88
S$472  (via drill 1 pad 1.78)
  other vias: 35.56,58.42
S$473  (via drill 1 pad 1.78)
  other vias: 38.1,58.42
S$474  (via drill 1 pad 1.78)
  other vias: 40.64,58.42
S$475  (via drill 1 pad 1.78)
  other vias: 43.18,58.42
S$476  (via drill 1 pad 1.78)
  other vias: 45.72,58.42
S$477  (via drill 1 pad 1.78)
  other vias: 48.26,58.42
S$478  (via drill 1 pad 1.78)
  other vias: 50.8,58.42
S$479  (via drill 1 pad 1.78)
  other vias: 53.34,58.42
S$480  (via drill 1 pad 1.78)
  other vias: 55.88,58.42
S$481  (via drill 1 pad 1.78)
  other vias: 58.42,58.42
S$482  (via drill 1 pad 1.78)
  other vias: 60.96,58.42
S$483  (via drill 1 pad 1.78)
  other vias: 63.5,58.42
S$484  (via drill 1 pad 1.78)
  other vias: 66.04,58.42
S$485  (via drill 1 pad 1.78)
  other vias: 68.58,55.88
S$486  (via drill 1 pad 1.78)
  other vias: 71.12,58.42
S$487  (via drill 1 pad 1.78)
  other vias: 73.66,58.42
S$488  (via drill 1 pad 1.78)
  other vias: 76.2,58.42
S$489  (via drill 1 pad 1.78)
  other vias: 68.58,58.42
S$490  (via drill 1 pad 1.78)
  other vias: 78.74,58.42
S$491  (via drill 1 pad 1.78)
  other vias: 81.28,58.42
S$492  (via drill 1 pad 1.78)
  other vias: 83.82,58.42
S$493  (via drill 1 pad 1.78)
  other vias: 86.36,58.42
S$494  (via drill 1 pad 1.78)
  other vias: 88.9,58.42
S$495  (via drill 1 pad 1.78)
  other vias: 91.44,55.88
S$496  (via drill 1 pad 1.78)
  other vias: 93.98,55.88
S$497  (via drill 1 pad 1.78)
  other vias: 81.28,40.64
S$498  (via drill 1 pad 1.78)
  other vias: 60.96,27.94
S$499  (via drill 1 pad 1.78)
  other vias: 78.74,20.32
S$500  (via drill 1 pad 1.78)
  other vias: 86.36,22.86
S$501  (via drill 1 pad 1.78)
  other vias: 93.98,27.94
S$502  (via drill 1 pad 1.78)
  other vias: 99.06,30.48
S$503  (via drill 1 pad 1.78)
  other vias: 99.06,35.56
S$504  (via drill 1 pad 1.78)
  other vias: 93.98,40.64
S$505  (via drill 1 pad 1.78)
  other vias: 40.64,38.1
S$506  (via drill 1 pad 1.78)
  other vias: 35.56,35.56
S$507  (via drill 1 pad 1.78)
  other vias: 30.48,33.02
S$508  (via drill 1 pad 1.78)
  other vias: 27.94,33.02
S$509  (via drill 1 pad 1.78)
  other vias: 25.4,48.26
S$510  (via drill 1 pad 1.78)
  other vias: 25.4,45.72
S$511  (via drill 1 pad 1.78)
  other vias: 91.44,58.42
S$512  (via drill 1 pad 1.78)
  other vias: 93.98,58.42
S$513  (via drill 1 pad 1.78)
  other vias: 96.52,58.42
S$514  (via drill 1 pad 1.78)
  other vias: 99.06,58.42
S$515  (via drill 1 pad 1.78)
  other vias: 101.6,58.42
S$516  (via drill 1 pad 1.78)
  other vias: 104.14,58.42
S$517  (via drill 1 pad 1.78)
  other vias: 106.68,58.42
S$518  (via drill 1 pad 1.78)
  other vias: 109.22,58.42
S$519  (via drill 1 pad 1.78)
  other vias: 111.76,55.88
S$520  (via drill 1 pad 1.78)
  other vias: 111.76,58.42
S$521  (via drill 1 pad 1.78)
  other vias: 116.84,58.42
S$522  (via drill 1 pad 1.78)
  other vias: 114.3,58.42
S$523  (via drill 1 pad 1.78)
  other vias: 119.38,58.42
S$524  (via drill 1 pad 1.78)
  other vias: 124.46,58.42
S$525  (via drill 1 pad 1.78)
  other vias: 121.92,58.42
S$526  (via drill 1 pad 1.78)
  other vias: 127,58.42
S$527  (via drill 1 pad 1.78)
  other vias: 129.54,58.42
S$528  (via drill 1 pad 1.78)
  other vias: 134.62,58.42
S$529  (via drill 1 pad 1.78)
  other vias: 132.08,58.42
S$530  (via drill 1 pad 1.78)
  other vias: 137.16,58.42
S$531  (via drill 1 pad 1.78)
  other vias: 12.7,55.88
S$532  (via drill 1 pad 1.78)
  other vias: 15.24,55.88
S$533  (via drill 1 pad 1.78)
  other vias: 17.78,55.88
S$534  (via drill 1 pad 1.78)
  other vias: 20.32,55.88
S$535  (via drill 1 pad 1.78)
  other vias: 22.86,53.34
S$536  (via drill 1 pad 1.78)
  other vias: 22.86,55.88
S$537  (via drill 1 pad 1.78)
  other vias: 25.4,55.88
S$538  (via drill 1 pad 1.78)
  other vias: 27.94,55.88
S$539  (via drill 1 pad 1.78)
  other vias: 30.48,55.88
S$540  (via drill 1 pad 1.78)
  other vias: 33.02,55.88
S$541  (via drill 1 pad 1.78)
  other vias: 38.1,55.88
S$542  (via drill 1 pad 1.78)
  other vias: 40.64,55.88
S$543  (via drill 1 pad 1.78)
  other vias: 43.18,55.88
S$544  (via drill 1 pad 1.78)
  other vias: 45.72,55.88
S$545  (via drill 1 pad 1.78)
  other vias: 48.26,55.88
S$546  (via drill 1 pad 1.78)
  other vias: 50.8,55.88
S$547  (via drill 1 pad 1.78)
  other vias: 53.34,55.88
S$548  (via drill 1 pad 1.78)
  other vias: 55.88,55.88
S$549  (via drill 1 pad 1.78)
  other vias: 58.42,55.88
S$550  (via drill 1 pad 1.78)
  other vias: 60.96,55.88
S$551  (via drill 1 pad 1.78)
  other vias: 63.5,55.88
S$552  (via drill 1 pad 1.78)
  other vias: 66.04,55.88
S$553  (via drill 1 pad 1.78)
  other vias: 71.12,55.88
S$554  (via drill 1 pad 1.78)
  other vias: 73.66,55.88
S$555  (via drill 1 pad 1.78)
  other vias: 76.2,55.88
S$556  (via drill 1 pad 1.78)
  other vias: 78.74,55.88
S$557  (via drill 1 pad 1.78)
  other vias: 81.28,55.88
S$558  (via drill 1 pad 1.78)
  other vias: 83.82,55.88
S$559  (via drill 1 pad 1.78)
  other vias: 86.36,55.88
S$560  (via drill 1 pad 1.78)
  other vias: 88.9,55.88
S$561  (via drill 1 pad 1.78)
  other vias: 96.52,55.88
S$562  (via drill 1 pad 1.78)
  other vias: 99.06,55.88
S$563  (via drill 1 pad 1.78)
  other vias: 165.1,55.88
S$564  (via drill 1 pad 1.78)
  other vias: 162.56,55.88
S$565  (via drill 1 pad 1.78)
  other vias: 160.02,55.88
S$566  (via drill 1 pad 1.78)
  other vias: 157.48,55.88
S$567  (via drill 1 pad 1.78)
  other vias: 154.94,55.88
S$568  (via drill 1 pad 1.78)
  other vias: 152.4,55.88
S$569  (via drill 1 pad 1.78)
  other vias: 149.86,55.88
S$570  (via drill 1 pad 1.78)
  other vias: 147.32,55.88
S$571  (via drill 1 pad 1.78)
  other vias: 142.24,55.88
S$572  (via drill 1 pad 1.78)
  other vias: 139.7,55.88
S$573  (via drill 1 pad 1.78)
  other vias: 137.16,55.88
S$574  (via drill 1 pad 1.78)
  other vias: 134.62,55.88
S$575  (via drill 1 pad 1.78)
  other vias: 132.08,55.88
S$576  (via drill 1 pad 1.78)
  other vias: 101.6,55.88
S$577  (via drill 1 pad 1.78)
  other vias: 104.14,55.88
S$578  (via drill 1 pad 1.78)
  other vias: 106.68,55.88
S$579  (via drill 1 pad 1.78)
  other vias: 109.22,55.88
S$580  (via drill 1 pad 1.78)
  other vias: 114.3,55.88
S$581  (via drill 1 pad 1.78)
  other vias: 116.84,55.88
S$582  (via drill 1 pad 1.78)
  other vias: 119.38,55.88
S$583  (via drill 1 pad 1.78)
  other vias: 121.92,55.88
S$584  (via drill 1 pad 1.78)
  other vias: 124.46,55.88
S$585  (via drill 1 pad 1.78)
  other vias: 127,55.88
S$586  (via drill 1 pad 1.78)
  other vias: 129.54,55.88
S$587  (via drill 1 pad 1.78)
  other vias: 12.7,53.34
S$588  (via drill 1 pad 1.78)
  other vias: 15.24,53.34
S$589  (via drill 1 pad 1.78)
  other vias: 17.78,53.34
S$590  (via drill 1 pad 1.78)
  other vias: 20.32,53.34
S$591  (via drill 1 pad 1.78)
  other vias: 25.4,53.34
S$592  (via drill 1 pad 1.78)
  other vias: 27.94,53.34
S$593  (via drill 1 pad 1.78)
  other vias: 30.48,53.34
S$594  (via drill 1 pad 1.78)
  other vias: 33.02,53.34
S$595  (via drill 1 pad 1.78)
  other vias: 35.56,53.34
S$596  (via drill 1 pad 1.78)
  other vias: 38.1,53.34
S$597  (via drill 1 pad 1.78)
  other vias: 40.64,53.34
S$598  (via drill 1 pad 1.78)
  other vias: 43.18,53.34
S$599  (via drill 1 pad 1.78)
  other vias: 45.72,53.34
S$600  (via drill 1 pad 1.78)
  other vias: 48.26,53.34
S$601  (via drill 1 pad 1.78)
  other vias: 50.8,53.34
S$602  (via drill 1 pad 1.78)
  other vias: 53.34,53.34
S$603  (via drill 1 pad 1.78)
  other vias: 55.88,53.34
S$604  (via drill 1 pad 1.78)
  other vias: 58.42,53.34
S$605  (via drill 1 pad 1.78)
  other vias: 60.96,53.34
S$606  (via drill 1 pad 1.78)
  other vias: 63.5,53.34
S$607  (via drill 1 pad 1.78)
  other vias: 66.04,53.34
S$608  (via drill 1 pad 1.78)
  other vias: 68.58,53.34
S$609  (via drill 1 pad 1.78)
  other vias: 71.12,53.34
S$610  (via drill 1 pad 1.78)
  other vias: 73.66,53.34
S$611  (via drill 1 pad 1.78)
  other vias: 76.2,53.34
S$612  (via drill 1 pad 1.78)
  other vias: 78.74,53.34
S$613  (via drill 1 pad 1.78)
  other vias: 81.28,53.34
S$614  (via drill 1 pad 1.78)
  other vias: 83.82,53.34
S$615  (via drill 1 pad 1.78)
  other vias: 86.36,53.34
S$616  (via drill 1 pad 1.78)
  other vias: 88.9,53.34
S$617  (via drill 1 pad 1.78)
  other vias: 91.44,53.34
S$618  (via drill 1 pad 1.78)
  other vias: 93.98,53.34
S$619  (via drill 1 pad 1.78)
  other vias: 96.52,53.34
S$620  (via drill 1 pad 1.78)
  other vias: 99.06,53.34
S$621  (via drill 1 pad 1.78)
  other vias: 101.6,53.34
S$622  (via drill 1 pad 1.78)
  other vias: 104.14,53.34
S$623  (via drill 1 pad 1.78)
  other vias: 106.68,53.34
S$624  (via drill 1 pad 1.78)
  other vias: 109.22,53.34
S$625  (via drill 1 pad 1.78)
  other vias: 111.76,53.34
S$626  (via drill 1 pad 1.78)
  other vias: 114.3,53.34
S$627  (via drill 1 pad 1.78)
  other vias: 116.84,53.34
S$628  (via drill 1 pad 1.78)
  other vias: 119.38,53.34
S$629  (via drill 1 pad 1.78)
  other vias: 121.92,53.34
S$630  (via drill 1 pad 1.78)
  other vias: 124.46,53.34
S$631  (via drill 1 pad 1.78)
  other vias: 127,53.34
S$632  (via drill 1 pad 1.78)
  other vias: 129.54,53.34
S$633  (via drill 1 pad 1.78)
  other vias: 132.08,53.34
S$634  (via drill 1 pad 1.78)
  other vias: 134.62,53.34
S$635  (via drill 1 pad 1.78)
  other vias: 137.16,53.34
S$636  (via drill 1 pad 1.78)
  other vias: 139.7,53.34
S$637  (via drill 1 pad 1.78)
  other vias: 142.24,53.34
S$638  (via drill 1 pad 1.78)
  other vias: 144.78,53.34
S$639  (via drill 1 pad 1.78)
  other vias: 147.32,53.34
S$640  (via drill 1 pad 1.78)
  other vias: 149.86,53.34
S$641  (via drill 1 pad 1.78)
  other vias: 152.4,53.34
S$642  (via drill 1 pad 1.78)
  other vias: 154.94,53.34
S$643  (via drill 1 pad 1.78)
  other vias: 157.48,53.34
S$644  (via drill 1 pad 1.78)
  other vias: 160.02,53.34
S$645  (via drill 1 pad 1.78)
  other vias: 162.56,53.34
S$646  (via drill 1 pad 1.78)
  other vias: 165.1,53.34
S$647  (via drill 1 pad 1.78)
  other vias: 165.1,50.8
S$648  (via drill 1 pad 1.78)
  other vias: 165.1,48.26
S$649  (via drill 1 pad 1.78)
  other vias: 165.1,45.72
S$650  (via drill 1 pad 1.78)
  other vias: 165.1,43.18
S$651  (via drill 1 pad 1.78)
  other vias: 165.1,40.64
S$652  (via drill 1 pad 1.78)
  other vias: 165.1,38.1
S$653  (via drill 1 pad 1.78)
  other vias: 165.1,35.56
S$654  (via drill 1 pad 1.78)
  other vias: 165.1,33.02
S$655  (via drill 1 pad 1.78)
  other vias: 165.1,30.48
S$656  (via drill 1 pad 1.78)
  other vias: 165.1,27.94
S$657  (via drill 1 pad 1.78)
  other vias: 165.1,25.4
S$658  (via drill 1 pad 1.78)
  other vias: 165.1,22.86
S$659  (via drill 1 pad 1.78)
  other vias: 165.1,20.32
S$660  (via drill 1 pad 1.78)
  other vias: 165.1,17.78
S$661  (via drill 1 pad 1.78)
  other vias: 165.1,15.24
S$662  (via drill 1 pad 1.78)
  other vias: 165.1,12.7
S$663  (via drill 1 pad 1.78)
  other vias: 162.56,12.7
S$664  (via drill 1 pad 1.78)
  other vias: 160.02,12.7
S$665  (via drill 1 pad 1.78)
  other vias: 157.48,12.7
S$666  (via drill 1 pad 1.78)
  other vias: 154.94,12.7
S$667  (via drill 1 pad 1.78)
  other vias: 152.4,12.7
S$668  (via drill 1 pad 1.78)
  other vias: 149.86,12.7
S$669  (via drill 1 pad 1.78)
  other vias: 147.32,12.7
S$670  (via drill 1 pad 1.78)
  other vias: 144.78,12.7
S$671  (via drill 1 pad 1.78)
  other vias: 142.24,12.7
S$672  (via drill 1 pad 1.78)
  other vias: 139.7,12.7
S$673  (via drill 1 pad 1.78)
  other vias: 137.16,12.7
S$674  (via drill 1 pad 1.78)
  other vias: 134.62,12.7
S$675  (via drill 1 pad 1.78)
  other vias: 132.08,12.7
S$676  (via drill 1 pad 1.78)
  other vias: 129.54,12.7
S$677  (via drill 1 pad 1.78)
  other vias: 127,12.7
S$678  (via drill 1 pad 1.78)
  other vias: 124.46,12.7
S$679  (via drill 1 pad 1.78)
  other vias: 121.92,12.7
S$680  (via drill 1 pad 1.78)
  other vias: 119.38,12.7
S$681  (via drill 1 pad 1.78)
  other vias: 12.7,50.8
S$682  (via drill 1 pad 1.78)
  other vias: 12.7,48.26
S$683  (via drill 1 pad 1.78)
  other vias: 12.7,45.72
S$684  (via drill 1 pad 1.78)
  other vias: 12.7,40.64
S$685  (via drill 1 pad 1.78)
  other vias: 12.7,43.18
S$686  (via drill 1 pad 1.78)
  other vias: 12.7,38.1
S$687  (via drill 1 pad 1.78)
  other vias: 12.7,35.56
S$688  (via drill 1 pad 1.78)
  other vias: 12.7,33.02
S$689  (via drill 1 pad 1.78)
  other vias: 12.7,30.48
S$690  (via drill 1 pad 1.78)
  other vias: 12.7,27.94
S$691  (via drill 1 pad 1.78)
  other vias: 12.7,25.4
S$692  (via drill 1 pad 1.78)
  other vias: 12.7,22.86
S$693  (via drill 1 pad 1.78)
  other vias: 12.7,20.32
S$694  (via drill 1 pad 1.78)
  other vias: 12.7,17.78
S$695  (via drill 1 pad 1.78)
  other vias: 12.7,15.24
S$696  (via drill 1 pad 1.78)
  other vias: 12.7,12.7
S$697  (via drill 1 pad 1.78)
  other vias: 15.24,12.7
S$698  (via drill 1 pad 1.78)
  other vias: 17.78,12.7
S$699  (via drill 1 pad 1.78)
  other vias: 20.32,12.7
S$700  (via drill 1 pad 1.78)
  other vias: 22.86,12.7
S$701  (via drill 1 pad 1.78)
  other vias: 25.4,12.7
S$702  (via drill 1 pad 1.78)
  other vias: 27.94,12.7
S$703  (via drill 1 pad 1.78)
  other vias: 30.48,12.7
S$704  (via drill 1 pad 1.78)
  other vias: 35.56,12.7
S$705  (via drill 1 pad 1.78)
  other vias: 33.02,12.7
S$706  (via drill 1 pad 1.78)
  other vias: 38.1,12.7
S$707  (via drill 1 pad 1.78)
  other vias: 40.64,12.7
S$708  (via drill 1 pad 1.78)
  other vias: 43.18,12.7
S$709  (via drill 1 pad 1.78)
  other vias: 45.72,12.7
S$710  (via drill 1 pad 1.78)
  other vias: 50.8,12.7
S$711  (via drill 1 pad 1.78)
  other vias: 48.26,12.7
S$712  (via drill 1 pad 1.78)
  other vias: 53.34,12.7
S$713  (via drill 1 pad 1.78)
  other vias: 55.88,12.7
S$714  (via drill 1 pad 1.78)
  other vias: 58.42,12.7
S$715  (via drill 1 pad 1.78)
  other vias: 60.96,12.7
S$716  (via drill 1 pad 1.78)
  other vias: 63.5,12.7
S$717  (via drill 1 pad 1.78)
  other vias: 66.04,12.7
S$718  (via drill 1 pad 1.78)
  other vias: 68.58,12.7
S$719  (via drill 1 pad 1.78)
  other vias: 71.12,12.7
S$720  (via drill 1 pad 1.78)
  other vias: 73.66,12.7
S$721  (via drill 1 pad 1.78)
  other vias: 76.2,12.7
S$722  (via drill 1 pad 1.78)
  other vias: 78.74,12.7
S$723  (via drill 1 pad 1.78)
  other vias: 81.28,12.7
S$724  (via drill 1 pad 1.78)
  other vias: 83.82,12.7
S$725  (via drill 1 pad 1.78)
  other vias: 86.36,12.7
S$726  (via drill 1 pad 1.78)
  other vias: 88.9,12.7
S$727  (via drill 1 pad 1.78)
  other vias: 91.44,12.7
S$728  (via drill 1 pad 1.78)
  other vias: 93.98,12.7
S$729  (via drill 1 pad 1.78)
  other vias: 96.52,12.7
S$730  (via drill 1 pad 1.78)
  other vias: 99.06,12.7
S$731  (via drill 1 pad 1.78)
  other vias: 101.6,12.7
S$732  (via drill 1 pad 1.78)
  other vias: 104.14,12.7
S$733  (via drill 1 pad 1.78)
  other vias: 106.68,12.7
S$734  (via drill 1 pad 1.78)
  other vias: 109.22,12.7
S$735  (via drill 1 pad 1.78)
  other vias: 111.76,12.7
S$736  (via drill 1 pad 1.78)
  other vias: 114.3,12.7
S$737  (via drill 1 pad 1.78)
  other vias: 116.84,12.7
S$738  (via drill 1 pad 1.78)
  other vias: 162.56,50.8
S$739  (via drill 1 pad 1.78)
  other vias: 162.56,48.26
S$740  (via drill 1 pad 1.78)
  other vias: 162.56,45.72
S$741  (via drill 1 pad 1.78)
  other vias: 162.56,43.18
S$742  (via drill 1 pad 1.78)
  other vias: 162.56,40.64
S$743  (via drill 1 pad 1.78)
  other vias: 162.56,38.1
S$744  (via drill 1 pad 1.78)
  other vias: 162.56,33.02
S$745  (via drill 1 pad 1.78)
  other vias: 162.56,35.56
S$746  (via drill 1 pad 1.78)
  other vias: 162.56,30.48
S$747  (via drill 1 pad 1.78)
  other vias: 162.56,27.94
S$748  (via drill 1 pad 1.78)
  other vias: 162.56,25.4
S$749  (via drill 1 pad 1.78)
  other vias: 162.56,22.86
S$750  (via drill 1 pad 1.78)
  other vias: 162.56,20.32
S$751  (via drill 1 pad 1.78)
  other vias: 162.56,17.78
S$752  (via drill 1 pad 1.78)
  other vias: 162.56,15.24
S$753  (via drill 1 pad 1.78)
  other vias: 160.02,15.24
S$754  (via drill 1 pad 1.78)
  other vias: 157.48,15.24
S$755  (via drill 1 pad 1.78)
  other vias: 154.94,15.24
S$756  (via drill 1 pad 1.78)
  other vias: 152.4,15.24
S$757  (via drill 1 pad 1.78)
  other vias: 149.86,15.24
S$758  (via drill 1 pad 1.78)
  other vias: 147.32,15.24
S$759  (via drill 1 pad 1.78)
  other vias: 144.78,15.24
S$760  (via drill 1 pad 1.78)
  other vias: 142.24,15.24
S$761  (via drill 1 pad 1.78)
  other vias: 139.7,15.24
S$762  (via drill 1 pad 1.78)
  other vias: 137.16,15.24
S$763  (via drill 1 pad 1.78)
  other vias: 134.62,15.24
S$764  (via drill 1 pad 1.78)
  other vias: 132.08,15.24
S$765  (via drill 1 pad 1.78)
  other vias: 129.54,15.24
S$766  (via drill 1 pad 1.78)
  other vias: 127,15.24
S$767  (via drill 1 pad 1.78)
  other vias: 124.46,15.24
S$768  (via drill 1 pad 1.78)
  other vias: 121.92,15.24
S$769  (via drill 1 pad 1.78)
  other vias: 119.38,15.24
S$770  (via drill 1 pad 1.78)
  other vias: 15.24,15.24
S$771  (via drill 1 pad 1.78)
  other vias: 15.24,50.8
S$772  (via drill 1 pad 1.78)
  other vias: 15.24,48.26
S$773  (via drill 1 pad 1.78)
  other vias: 15.24,45.72
S$774  (via drill 1 pad 1.78)
  other vias: 15.24,43.18
S$775  (via drill 1 pad 1.78)
  other vias: 15.24,40.64
S$776  (via drill 1 pad 1.78)
  other vias: 15.24,38.1
S$777  (via drill 1 pad 1.78)
  other vias: 15.24,35.56
S$778  (via drill 1 pad 1.78)
  other vias: 15.24,33.02
S$779  (via drill 1 pad 1.78)
  other vias: 15.24,30.48
S$780  (via drill 1 pad 1.78)
  other vias: 15.24,27.94
S$781  (via drill 1 pad 1.78)
  other vias: 15.24,25.4
S$782  (via drill 1 pad 1.78)
  other vias: 15.24,22.86
S$783  (via drill 1 pad 1.78)
  other vias: 15.24,20.32
S$784  (via drill 1 pad 1.78)
  other vias: 15.24,17.78
S$785  (via drill 1 pad 1.78)
  other vias: 17.78,15.24
S$786  (via drill 1 pad 1.78)
  other vias: 20.32,15.24
S$787  (via drill 1 pad 1.78)
  other vias: 22.86,15.24
S$788  (via drill 1 pad 1.78)
  other vias: 25.4,15.24
S$789  (via drill 1 pad 1.78)
  other vias: 27.94,15.24
S$790  (via drill 1 pad 1.78)
  other vias: 30.48,15.24
S$791  (via drill 1 pad 1.78)
  other vias: 33.02,15.24
S$792  (via drill 1 pad 1.78)
  other vias: 35.56,15.24
S$793  (via drill 1 pad 1.78)
  other vias: 38.1,15.24
S$794  (via drill 1 pad 1.78)
  other vias: 40.64,15.24
S$795  (via drill 1 pad 1.78)
  other vias: 43.18,15.24
S$796  (via drill 1 pad 1.78)
  other vias: 45.72,15.24
S$797  (via drill 1 pad 1.78)
  other vias: 48.26,15.24
S$798  (via drill 1 pad 1.78)
  other vias: 50.8,15.24
S$799  (via drill 1 pad 1.78)
  other vias: 53.34,15.24
S$800  (via drill 1 pad 1.78)
  other vias: 55.88,15.24
S$801  (via drill 1 pad 1.78)
  other vias: 60.96,15.24
S$802  (via drill 1 pad 1.78)
  other vias: 58.42,15.24
S$803  (via drill 1 pad 1.78)
  other vias: 63.5,15.24
S$804  (via drill 1 pad 1.78)
  other vias: 66.04,15.24
S$805  (via drill 1 pad 1.78)
  other vias: 68.58,15.24
S$806  (via drill 1 pad 1.78)
  other vias: 71.12,15.24
S$807  (via drill 1 pad 1.78)
  other vias: 73.66,15.24
S$808  (via drill 1 pad 1.78)
  other vias: 76.2,15.24
S$809  (via drill 1 pad 1.78)
  other vias: 78.74,15.24
S$810  (via drill 1 pad 1.78)
  other vias: 81.28,15.24
S$811  (via drill 1 pad 1.78)
  other vias: 83.82,15.24
S$812  (via drill 1 pad 1.78)
  other vias: 86.36,15.24
S$813  (via drill 1 pad 1.78)
  other vias: 88.9,15.24
S$814  (via drill 1 pad 1.78)
  other vias: 91.44,15.24
S$815  (via drill 1 pad 1.78)
  other vias: 96.52,15.24
S$816  (via drill 1 pad 1.78)
  other vias: 93.98,15.24
S$817  (via drill 1 pad 1.78)
  other vias: 99.06,15.24
S$818  (via drill 1 pad 1.78)
  other vias: 101.6,15.24
S$819  (via drill 1 pad 1.78)
  other vias: 106.68,15.24
S$820  (via drill 1 pad 1.78)
  other vias: 104.14,15.24
S$821  (via drill 1 pad 1.78)
  other vias: 109.22,15.24
S$822  (via drill 1 pad 1.78)
  other vias: 111.76,15.24
S$823  (via drill 1 pad 1.78)
  other vias: 114.3,15.24
S$824  (via drill 1 pad 1.78)
  other vias: 116.84,15.24
S$825  (via drill 1 pad 1.78)
  other vias: 160.02,50.8
S$826  (via drill 1 pad 1.78)
  other vias: 160.02,48.26
S$827  (via drill 1 pad 1.78)
  other vias: 160.02,45.72
S$828  (via drill 1 pad 1.78)
  other vias: 160.02,43.18
S$829  (via drill 1 pad 1.78)
  other vias: 160.02,40.64
S$830  (via drill 1 pad 1.78)
  other vias: 160.02,38.1
S$831  (via drill 1 pad 1.78)
  other vias: 160.02,35.56
S$832  (via drill 1 pad 1.78)
  other vias: 160.02,33.02
S$833  (via drill 1 pad 1.78)
  other vias: 160.02,30.48
S$834  (via drill 1 pad 1.78)
  other vias: 160.02,27.94
S$835  (via drill 1 pad 1.78)
  other vias: 160.02,25.4
S$836  (via drill 1 pad 1.78)
  other vias: 160.02,22.86
S$837  (via drill 1 pad 1.78)
  other vias: 160.02,20.32
S$838  (via drill 1 pad 1.78)
  other vias: 160.02,17.78
S$839  (via drill 1 pad 1.78)
  other vias: 17.78,50.8
S$840  (via drill 1 pad 1.78)
  other vias: 20.32,50.8
S$841  (via drill 1 pad 1.78)
  other vias: 22.86,50.8
S$842  (via drill 1 pad 1.78)
  other vias: 27.94,50.8
S$843  (via drill 1 pad 1.78)
  other vias: 25.4,50.8
S$844  (via drill 1 pad 1.78)
  other vias: 30.48,50.8
S$845  (via drill 1 pad 1.78)
  other vias: 33.02,50.8
S$846  (via drill 1 pad 1.78)
  other vias: 35.56,50.8
S$847  (via drill 1 pad 1.78)
  other vias: 38.1,50.8
S$848  (via drill 1 pad 1.78)
  other vias: 43.18,50.8
S$849  (via drill 1 pad 1.78)
  other vias: 40.64,50.8
S$850  (via drill 1 pad 1.78)
  other vias: 45.72,50.8
S$851  (via drill 1 pad 1.78)
  other vias: 48.26,50.8
S$852  (via drill 1 pad 1.78)
  other vias: 53.34,50.8
S$853  (via drill 1 pad 1.78)
  other vias: 50.8,50.8
S$854  (via drill 1 pad 1.78)
  other vias: 55.88,50.8
S$855  (via drill 1 pad 1.78)
  other vias: 58.42,50.8
S$856  (via drill 1 pad 1.78)
  other vias: 60.96,50.8
S$857  (via drill 1 pad 1.78)
  other vias: 66.04,50.8
S$858  (via drill 1 pad 1.78)
  other vias: 63.5,50.8
S$859  (via drill 1 pad 1.78)
  other vias: 68.58,50.8
S$860  (via drill 1 pad 1.78)
  other vias: 71.12,48.26
S$861  (via drill 1 pad 1.78)
  other vias: 71.12,50.8
S$862  (via drill 1 pad 1.78)
  other vias: 73.66,50.8
S$863  (via drill 1 pad 1.78)
  other vias: 76.2,50.8
S$864  (via drill 1 pad 1.78)
  other vias: 78.74,50.8
S$865  (via drill 1 pad 1.78)
  other vias: 81.28,50.8
S$866  (via drill 1 pad 1.78)
  other vias: 83.82,50.8
S$867  (via drill 1 pad 1.78)
  other vias: 86.36,50.8
S$868  (via drill 1 pad 1.78)
  other vias: 88.9,50.8
S$869  (via drill 1 pad 1.78)
  other vias: 91.44,50.8
S$870  (via drill 1 pad 1.78)
  other vias: 93.98,50.8
S$871  (via drill 1 pad 1.78)
  other vias: 96.52,50.8
S$872  (via drill 1 pad 1.78)
  other vias: 99.06,50.8
S$873  (via drill 1 pad 1.78)
  other vias: 101.6,50.8
S$874  (via drill 1 pad 1.78)
  other vias: 104.14,50.8
S$875  (via drill 1 pad 1.78)
  other vias: 106.68,50.8
S$876  (via drill 1 pad 1.78)
  other vias: 109.22,50.8
S$877  (via drill 1 pad 1.78)
  other vias: 111.76,50.8
S$878  (via drill 1 pad 1.78)
  other vias: 114.3,50.8
S$879  (via drill 1 pad 1.78)
  other vias: 116.84,50.8
S$880  (via drill 1 pad 1.78)
  other vias: 119.38,50.8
